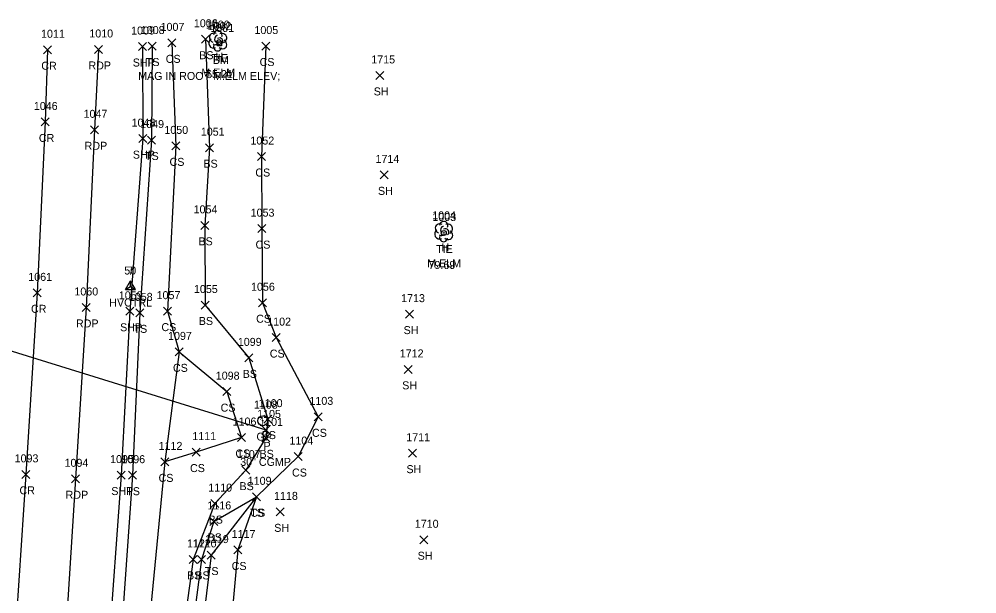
# Model space of a CAD drawing. Extents: x 1443960 to 1446865, y 610387 to 616706.
# Drawn here: x 1446612.8 to 1446852.1, y 611314.4 to 611458.2 of the extents above; entities that cross this region are included whole.
import ezdxf

# ---------------------------------------------------------------- set-up
doc = ezdxf.new("R2010")
doc.units = 0
for name, color, linetype in [('C_A', 7, 'Continuous'), ('C_C', 7, 'Continuous'), ('C_I', 7, 'Continuous'), ('CBP', 7, 'Continuous'), ('CPBM', 7, 'Continuous'), ('CPSM', 7, 'Continuous'), ('D_A', 7, 'Continuous'), ('D_C', 7, 'Continuous'), ('D_I', 7, 'Continuous'), ('D_TIC', 7, 'Continuous'), ('DCP', 7, 'Continuous'), ('L_A', 7, 'Continuous'), ('L_C', 7, 'Continuous'), ('L_I', 7, 'Continuous'), ('L_TIC', 7, 'Continuous'), ('LELB', 7, 'Continuous'), ('LTD', 7, 'Continuous'), ('P_A', 7, 'Continuous'), ('P_I', 7, 'Continuous'), ('P_TIC', 7, 'Continuous'), ('PET', 7, 'Continuous'), ('PRC', 7, 'Continuous'), ('PSP', 7, 'Continuous'), ('R_A', 7, 'Continuous'), ('R_I', 7, 'Continuous'), ('RGP', 7, 'Continuous')]:
    doc.layers.add(name, color=color, linetype=linetype)

msp = doc.modelspace()

# ---------------------------------------------------------------- linework, layer by layer
at = {"layer": 'CBP'}
for centre, radius in [((1446662.7, 611452.41), 0.625), ((1446662.7, 611452.41), 0.0833), ((1446718.89, 611404.66), 0.625), ((1446718.89, 611404.66), 0.0833)]:
    msp.add_circle(centre, radius, dxfattribs=at)
at = {"layer": 'CPBM'}
for p, q in [((1446662.33, 611451.44), (1446662.33, 611452.44)), ((1446662.33, 611452.44), (1446663.33, 611452.44)), ((1446662.83, 611451.94), (1446662.83, 611451.94)), ((1446662.83, 611451.94), (1446662.83, 611451.94)), ((1446663.33, 611452.44), (1446663.33, 611451.44)), ((1446663.33, 611451.44), (1446662.33, 611451.44))]:
    msp.add_line(p, q, dxfattribs=at)
at = {"layer": 'CPSM'}
for p, q in [((1446639.33, 611390.55), (1446640.58, 611392.71)), ((1446639.33, 611390.55), (1446640.58, 611392.71)), ((1446641.83, 611390.55), (1446640.58, 611392.71)), ((1446640.58, 611391.27), (1446640.58, 611392.71)), ((1446641.83, 611390.55), (1446640.58, 611392.71)), ((1446640.58, 611391.27), (1446640.58, 611392.71)), ((1446639.33, 611390.55), (1446640.58, 611391.27)), ((1446639.33, 611390.55), (1446640.58, 611391.27)), ((1446639.33, 611390.55), (1446641.83, 611390.55)), ((1446639.33, 611390.55), (1446641.83, 611390.55)), ((1446640.58, 611391.27), (1446640.58, 611391.27)), ((1446640.58, 611391.27), (1446641.83, 611390.55)), ((1446640.58, 611391.27), (1446640.58, 611391.27)), ((1446640.58, 611391.27), (1446641.83, 611390.55))]:
    msp.add_line(p, q, dxfattribs=at)
at = {"layer": 'D_TIC'}
for points in [[(1446673.45, 611354.4), (1446675.45, 611356.4)], [(1446675.45, 611354.4), (1446673.45, 611356.4)]]:
    msp.add_lwpolyline(points, dxfattribs=at)
at = {"layer": 'DCP'}
msp.add_lwpolyline([(1446557.44, 611391.72), (1446674.45, 611355.4)], dxfattribs=at)
at = {"layer": 'L_TIC'}
for points in [[(1446658.32, 611452.13), (1446660.32, 611454.13)], [(1446660.32, 611452.13), (1446658.32, 611454.13)], [(1446645.01, 611450.43), (1446647.01, 611452.43)], [(1446647.01, 611450.43), (1446645.01, 611452.43)], [(1446649.95, 611451.22), (1446651.95, 611453.22)], [(1446651.95, 611451.22), (1446649.95, 611453.22)], [(1446673.41, 611450.43), (1446675.41, 611452.43)], [(1446675.41, 611450.43), (1446673.41, 611452.43)], [(1446701.89, 611443.07), (1446703.89, 611445.07)], [(1446703.89, 611443.07), (1446701.89, 611445.07)], [(1446644.8, 611426.91), (1446646.8, 611428.91)], [(1446646.8, 611426.91), (1446644.8, 611428.91)], [(1446650.9, 611425.45), (1446652.9, 611427.45)], [(1446652.9, 611425.45), (1446650.9, 611427.45)], [(1446659.37, 611425), (1446661.37, 611427)], [(1446661.37, 611425), (1446659.37, 611427)], [(1446672.33, 611422.78), (1446674.33, 611424.78)], [(1446674.33, 611422.78), (1446672.33, 611424.78)], [(1446702.95, 611418.2), (1446704.95, 611420.2)], [(1446704.95, 611418.2), (1446702.95, 611420.2)], [(1446658.13, 611405.57), (1446660.13, 611407.57)], [(1446660.13, 611405.57), (1446658.13, 611407.57)], [(1446672.4, 611404.75), (1446674.4, 611406.75)], [(1446674.4, 611404.75), (1446672.4, 611406.75)], [(1446658.21, 611385.64), (1446660.21, 611387.64)], [(1446660.21, 611385.64), (1446658.21, 611387.64)], [(1446672.54, 611386.21), (1446674.54, 611388.21)], [(1446674.54, 611386.21), (1446672.54, 611388.21)], [(1446641.94, 611383.68), (1446643.94, 611385.68)], [(1446643.94, 611383.68), (1446641.94, 611385.68)], [(1446648.87, 611384.11), (1446650.87, 611386.11)], [(1446650.87, 611384.11), (1446648.87, 611386.11)], [(1446709.36, 611383.36), (1446711.36, 611385.36)], [(1446711.36, 611383.36), (1446709.36, 611385.36)], [(1446675.96, 611377.49), (1446677.96, 611379.49)], [(1446677.96, 611377.49), (1446675.96, 611379.49)], [(1446651.75, 611373.92), (1446653.75, 611375.92)], [(1446653.75, 611373.92), (1446651.75, 611375.92)], [(1446651.75, 611373.92), (1446653.75, 611375.92)], [(1446653.75, 611373.92), (1446651.75, 611375.92)], [(1446669.19, 611372.42), (1446671.19, 611374.42)], [(1446671.19, 611372.42), (1446669.19, 611374.42)], [(1446709.01, 611369.54), (1446711.01, 611371.54)], [(1446711.01, 611369.54), (1446709.01, 611371.54)], [(1446663.67, 611363.97), (1446665.67, 611365.97)], [(1446665.67, 611363.97), (1446663.67, 611365.97)], [(1446673.94, 611357.1), (1446675.94, 611359.1)], [(1446675.94, 611357.1), (1446673.94, 611359.1)], [(1446686.51, 611357.67), (1446688.51, 611359.67)], [(1446688.51, 611357.67), (1446686.51, 611359.67)], [(1446667.37, 611352.5), (1446669.37, 611354.5)], [(1446669.37, 611352.5), (1446667.37, 611354.5)], [(1446673.39, 611352.41), (1446675.39, 611354.41)], [(1446675.39, 611352.41), (1446673.39, 611354.41)], [(1446656.02, 611348.85), (1446658.02, 611350.85)], [(1446658.02, 611348.85), (1446656.02, 611350.85)], [(1446681.52, 611347.73), (1446683.52, 611349.73)], [(1446683.52, 611347.73), (1446681.52, 611349.73)], [(1446710.08, 611348.58), (1446712.08, 611350.58)], [(1446712.08, 611348.58), (1446710.08, 611350.58)], [(1446648.16, 611346.4), (1446650.16, 611348.4)], [(1446650.16, 611346.4), (1446648.16, 611348.4)], [(1446648.16, 611346.4), (1446650.16, 611348.4)], [(1446650.16, 611346.4), (1446648.16, 611348.4)], [(1446640.12, 611343.07), (1446642.12, 611345.07)], [(1446642.12, 611343.07), (1446640.12, 611345.07)], [(1446668.38, 611344.33), (1446670.38, 611346.33)], [(1446670.38, 611344.33), (1446668.38, 611346.33)], [(1446671.1, 611337.67), (1446673.1, 611339.67)], [(1446673.1, 611337.67), (1446671.1, 611339.67)], [(1446671.1, 611337.67), (1446673.1, 611339.67)], [(1446673.1, 611337.67), (1446671.1, 611339.67)], [(1446660.68, 611335.96), (1446662.68, 611337.96)], [(1446662.68, 611335.96), (1446660.68, 611337.96)], [(1446677.03, 611333.9), (1446679.03, 611335.9)], [(1446679.03, 611333.9), (1446677.03, 611335.9)], [(1446660.42, 611331.51), (1446662.42, 611333.51)], [(1446662.42, 611331.51), (1446660.42, 611333.51)], [(1446712.87, 611326.92), (1446714.87, 611328.92)], [(1446714.87, 611326.92), (1446712.87, 611328.92)], [(1446659.75, 611323.09), (1446661.75, 611325.09)], [(1446661.75, 611323.09), (1446659.75, 611325.09)], [(1446666.43, 611324.36), (1446668.43, 611326.36)], [(1446668.43, 611324.36), (1446666.43, 611326.36)], [(1446655.28, 611322), (1446657.28, 611324)], [(1446657.28, 611322), (1446655.28, 611324)], [(1446657.36, 611322), (1446659.36, 611324)], [(1446659.36, 611322), (1446657.36, 611324)]]:
    msp.add_lwpolyline(points, dxfattribs=at)
at = {"layer": 'LELB'}
for points in [[(1446650.95, 611452.22), (1446651.9, 611426.45), (1446649.87, 611385.11), (1446652.75, 611374.92), (1446649.16, 611347.4), (1446644.4, 611298.29), (1446641.62, 611252.48), (1446636.15, 611208.65), (1446631.11, 611163.63), (1446633.53, 611158.95), (1446637.37, 611162.3), (1446642.9, 611148.76), (1446645.64, 611144.28), (1446654.29, 611138.48), (1446692.29, 611116.85), (1446724.64, 611106.48), (1446767.02, 611093.78), (1446771.54, 611085.7), (1446779.15, 611079.3), (1446804.37, 611061.23), (1446846.91, 611054.82)], [(1446659.32, 611453.13), (1446660.37, 611426), (1446659.13, 611406.57), (1446659.21, 611386.64), (1446670.19, 611373.42), (1446674.94, 611358.1), (1446674.39, 611353.41), (1446669.38, 611345.33), (1446661.68, 611336.96), (1446656.28, 611323), (1446652.61, 611296.67), (1446649.33, 611250.55), (1446643.71, 611210.42), (1446642.98, 611161.02)], [(1446646.01, 611451.43), (1446645.8, 611427.91), (1446642.94, 611384.68), (1446641.12, 611344.07), (1446637.9, 611299.18), (1446633.76, 611254.36), (1446628.53, 611208.76), (1446626.59, 611161.02), (1446631.89, 611151.52), (1446639.4, 611144.52), (1446638.89, 611137.35), (1446641.22, 611135.35), (1446691.88, 611109.53), (1446720.61, 611092.87), (1446765.35, 611070.86), (1446803.04, 611049.45), (1446832.29, 611033.43)], [(1446674.41, 611451.43), (1446673.33, 611423.78), (1446673.4, 611405.75), (1446673.54, 611387.21), (1446676.96, 611378.49), (1446687.51, 611358.67), (1446682.52, 611348.73), (1446672.1, 611338.67), (1446667.43, 611325.36), (1446664.64, 611295.09), (1446664.71, 611246.97), (1446665.06, 611207.83), (1446662.27, 611160.47), (1446692.58, 611128.32), (1446729.03, 611120.7), (1446764.81, 611100.69), (1446774.62, 611095.27), (1446783.7, 611091.47), (1446810.78, 611080.25), (1446852.14, 611066.22)], [(1446652.75, 611374.92), (1446664.67, 611364.97), (1446668.37, 611353.5), (1446657.02, 611349.85), (1446649.16, 611347.4)], [(1446672.1, 611338.67), (1446660.75, 611324.09), (1446657.32, 611296.21), (1446653.24, 611250), (1446649.33, 611209.24), (1446649.16, 611162.92), (1446654.29, 611138.48)], [(1446661.42, 611332.51), (1446672.1, 611338.67)], [(1446661.42, 611332.51), (1446658.36, 611323), (1446654.87, 611296.43), (1446651.95, 611250.23), (1446646.19, 611210.4), (1446642.98, 611161.02)]]:
    msp.add_lwpolyline(points, dxfattribs=at)
at = {"layer": 'LTD'}
for p, q in [((1446662.37, 611452.79), (1446662.37, 611452.79)), ((1446662.37, 611452.79), (1446662.37, 611452.79)), ((1446718.85, 611405.07), (1446718.85, 611405.07)), ((1446718.85, 611405.07), (1446718.85, 611405.07))]:
    msp.add_line(p, q, dxfattribs=at)
for centre in [(1446662.42, 611454.22), (1446718.9, 611406.51)]:
    msp.add_arc(centre, 1.05, 335.5272, 180.9563, dxfattribs=at)
for centre, major_axis, ratio, start_param, end_param in [((1446661.58, 611453.46), (1.21, -0.51), 0.895232, 1.570796, 4.712389), ((1446662.16, 611453.25), (-0.208, -0.792), 0.645439, 3.141593, 6.283185), ((1446663.41, 611453.37), (-1.14, -0.48), 0.949671, 1.570796, 4.712389), ((1446661.29, 611452.08), (0.58, -1.04), 0.959034, 3.141593, 6.283185), ((1446661.91, 611452.04), (-0.625, -0.083), 0.423636, 0, 3.141593), ((1446662.87, 611452.62), (-0.5, 0.667), 0.989748, 3.141593, 6.283185), ((1446663.37, 611451.96), (-1.09, 0.79), 0.841452, 1.570796, 4.712389), ((1446662.37, 611451.29), (0.26, 1.06), 0.942809, 1.570796, 4.712389), ((1446718.06, 611405.74), (1.21, -0.51), 0.895232, 1.570796, 4.712389), ((1446718.64, 611405.53), (-0.208, -0.792), 0.645439, 3.141593, 6.283185), ((1446719.89, 611405.66), (-1.14, -0.48), 0.949671, 1.570796, 4.712389), ((1446717.77, 611404.36), (0.58, -1.04), 0.959034, 3.141593, 6.283185), ((1446718.39, 611404.32), (-0.625, -0.083), 0.423636, 0, 3.141593), ((1446719.35, 611404.91), (-0.5, 0.667), 0.989748, 3.141593, 6.283185), ((1446719.85, 611404.24), (-1.09, 0.79), 0.841452, 1.570796, 4.712389), ((1446718.85, 611403.57), (0.26, 1.06), 0.942809, 1.570796, 4.712389)]:
    msp.add_ellipse(centre, major_axis=major_axis, ratio=ratio, start_param=start_param, end_param=end_param, dxfattribs=at)
at = {"layer": 'P_TIC'}
for points in [[(1446642.6, 611450.3), (1446644.6, 611452.3)], [(1446644.6, 611450.3), (1446642.6, 611452.3)], [(1446618.86, 611449.5), (1446620.86, 611451.5)], [(1446620.86, 611449.5), (1446618.86, 611451.5)], [(1446631.58, 611449.57), (1446633.58, 611451.57)], [(1446633.58, 611449.57), (1446631.58, 611451.57)], [(1446618.25, 611431.43), (1446620.25, 611433.43)], [(1446620.25, 611431.43), (1446618.25, 611433.43)], [(1446630.62, 611429.47), (1446632.62, 611431.47)], [(1446632.62, 611429.47), (1446630.62, 611431.47)], [(1446642.63, 611427.26), (1446644.63, 611429.26)], [(1446644.63, 611427.26), (1446642.63, 611429.26)], [(1446616.28, 611388.69), (1446618.28, 611390.69)], [(1446618.28, 611388.69), (1446616.28, 611390.69)], [(1446628.46, 611385.03), (1446630.46, 611387.03)], [(1446630.46, 611385.03), (1446628.46, 611387.03)], [(1446639.44, 611384.07), (1446641.44, 611386.07)], [(1446641.44, 611384.07), (1446639.44, 611386.07)], [(1446613.4, 611343.28), (1446615.4, 611345.28)], [(1446615.4, 611343.28), (1446613.4, 611345.28)], [(1446625.87, 611342.17), (1446627.87, 611344.17)], [(1446627.87, 611342.17), (1446625.87, 611344.17)], [(1446637.25, 611343.1), (1446639.25, 611345.1)], [(1446639.25, 611343.1), (1446637.25, 611345.1)]]:
    msp.add_lwpolyline(points, dxfattribs=at)
at = {"layer": 'PET'}
msp.add_lwpolyline([(1446632.58, 611450.57), (1446631.62, 611430.47), (1446629.46, 611386.03), (1446626.87, 611343.17), (1446624.08, 611299.75), (1446620.8, 611255.87), (1446617.26, 611209.52), (1446613.17, 611162.1), (1446611.04, 611142.08)], dxfattribs=at)
at = {"layer": 'PRC'}
msp.add_lwpolyline([(1446619.86, 611450.5), (1446619.25, 611432.43), (1446617.28, 611389.69), (1446614.4, 611344.28), (1446611.54, 611300.05), (1446608.09, 611257.25), (1446604.45, 611210.89), (1446600.19, 611163.97), (1446598.97, 611148.35)], dxfattribs=at)
at = {"layer": 'PSP'}
msp.add_lwpolyline([(1446643.6, 611451.3), (1446643.63, 611428.26), (1446640.44, 611385.07), (1446638.25, 611344.1), (1446635.02, 611299.39), (1446631.16, 611255.01), (1446627.07, 611208.74), (1446623.04, 611160.92), (1446621.65, 611145.45), (1446620.1, 611138.33), (1446620.36, 611137.27)], dxfattribs=at)
at = {"layer": 'RGP'}
msp.add_line((1446673.64, 611357.71), (1446673.64, 611357.71), dxfattribs=at)
for radius in [1.25, 0.0833]:
    msp.add_circle((1446673.64, 611357.71), radius, dxfattribs=at)

# ---------------------------------------------------------------- texts
at = {"layer": 'C_A'}
for s, p in [('TIE', (1446660.78, 611447.41)), ('BM', (1446661.15, 611446.94)), ('TIE', (1446716.97, 611399.66)), ('HVCTRL', (1446635.27, 611386.27)), ('HVCTRL', (1446635.27, 611386.27))]:
    msp.add_text(s, height=2, dxfattribs=at).set_placement(p)
at = {"layer": 'C_C'}
for s, p in [('MAG IN ROOT M.ELM ELEV;', (1446642.5, 611442.94)), ('65.21', (1446659.47, 611443.41)), ('79.69', (1446715.09, 611395.66))]:
    msp.add_text(s, height=2, dxfattribs=at).set_placement(p)
at = {"layer": 'C_I'}
for s, p in [('1002', (1446659.85, 611455.41)), ('1001', (1446660.55, 611454.94)), ('1003', (1446716.04, 611407.66)), ('50', (1446639.03, 611394.27)), ('7', (1446640.01, 611394.27))]:
    msp.add_text(s, height=2, dxfattribs=at).set_placement(p)
at = {"layer": 'D_A'}
msp.add_text('P', height=2, dxfattribs=at).set_placement((1446673.82, 611350.4))
at = {"layer": 'D_C'}
msp.add_text('30" CGMP', height=2, dxfattribs=at).set_placement((1446668.01, 611346.4))
at = {"layer": 'D_I'}
msp.add_text('1105', height=2, dxfattribs=at).set_placement((1446672.24, 611358.4))
at = {"layer": 'L_A'}
for s, p in [('BS', (1446657.76, 611448.13)), ('H', (1446661.81, 611447.79)), ('TS', (1446644.42, 611446.43)), ('CS', (1446649.39, 611447.22)), ('CS', (1446672.85, 611446.43)), ('SH', (1446701.38, 611439.07)), ('TS', (1446644.21, 611422.91)), ('CS', (1446650.34, 611421.45)), ('BS', (1446658.81, 611421)), ('CS', (1446671.78, 611418.78)), ('SH', (1446702.44, 611414.2)), ('BS', (1446657.57, 611401.57)), ('CS', (1446671.84, 611400.75)), ('H', (1446718.29, 611400.07)), ('BS', (1446657.65, 611381.64)), ('CS', (1446671.98, 611382.21)), ('TS', (1446641.35, 611379.68)), ('CS', (1446648.31, 611380.11)), ('SH', (1446708.85, 611379.36)), ('CS', (1446675.4, 611373.49)), ('CS', (1446651.19, 611369.92)), ('CS', (1446651.19, 611369.92)), ('BS', (1446668.63, 611368.42)), ('SH', (1446708.5, 611365.54)), ('CS', (1446663.11, 611359.97)), ('BS', (1446673.38, 611353.1)), ('CS', (1446685.95, 611353.67)), ('CS', (1446666.81, 611348.5)), ('BS', (1446672.83, 611348.41)), ('CS', (1446655.46, 611344.85)), ('SH', (1446709.57, 611344.58)), ('CS', (1446647.6, 611342.4)), ('CS', (1446647.6, 611342.4)), ('CS', (1446680.96, 611343.73)), ('BS', (1446667.82, 611340.33)), ('TS', (1446639.53, 611339.07)), ('TS', (1446670.51, 611333.67)), ('CS', (1446670.54, 611333.67)), ('BS', (1446660.12, 611331.96)), ('SH', (1446676.51, 611329.9)), ('BS', (1446659.86, 611327.51)), ('SH', (1446712.36, 611322.92)), ('TS', (1446659.16, 611319.09)), ('CS', (1446665.87, 611320.36)), ('BS', (1446654.72, 611318)), ('BS', (1446656.8, 611318))]:
    msp.add_text(s, height=2, dxfattribs=at).set_placement(p)
at = {"layer": 'L_C'}
for p in [(1446658.28, 611443.79), (1446714.76, 611396.07)]:
    msp.add_text('M.ELM', height=2, dxfattribs=at).set_placement(p)
at = {"layer": 'L_I'}
for s, p in [('1007', (1446648.1, 611455.22)), ('1006', (1446656.42, 611456.13)), ('1000', (1446659.44, 611455.79)), ('1008', (1446643.16, 611454.43)), ('1005', (1446671.56, 611454.43)), ('1715', (1446700.77, 611447.07)), ('1049', (1446643.02, 611430.91)), ('1050', (1446649.05, 611429.45)), ('1051', (1446658.16, 611429)), ('1052', (1446670.56, 611426.78)), ('1714', (1446701.83, 611422.2)), ('1054', (1446656.36, 611409.57)), ('1053', (1446670.62, 611408.75)), ('1004', (1446716, 611408.07)), ('1056', (1446670.71, 611390.21)), ('1058', (1446640.17, 611387.68)), ('1057', (1446647.1, 611388.11)), ('1055', (1446656.44, 611389.64)), ('1713', (1446708.23, 611387.36)), ('1102', (1446674.76, 611381.49)), ('1097', (1446649.97, 611377.92)), ('1097', (1446649.97, 611377.92)), ('1099', (1446667.41, 611376.42)), ('1712', (1446707.89, 611373.54)), ('1098', (1446661.9, 611367.97)), ('1103', (1446685.31, 611361.67)), ('1100', (1446672.65, 611361.1)), ('1106', (1446666.11, 611356.5)), ('1101', (1446672.75, 611356.41)), ('1111', (1446656.03, 611352.85)), ('1104', (1446680.31, 611351.73)), ('1711', (1446709.52, 611352.58)), ('1112', (1446647.6, 611350.4)), ('1112', (1446647.6, 611350.4)), ('1096', (1446638.29, 611347.07)), ('1107', (1446667.18, 611348.33)), ('1110', (1446660.03, 611339.96)), ('1109', (1446669.89, 611341.67)), ('1109', (1446669.89, 611341.67)), ('1118', (1446676.47, 611337.9)), ('1116', (1446659.8, 611335.51)), ('1710', (1446711.65, 611330.92)), ('1117', (1446665.87, 611328.36)), ('1121', (1446654.72, 611326)), ('1120', (1446656.15, 611326)), ('1119', (1446659.19, 611327.09))]:
    msp.add_text(s, height=2, dxfattribs=at).set_placement(p)
at = {"layer": 'P_A'}
for s, p in [('CR', (1446618.29, 611445.5)), ('RDP', (1446630.07, 611445.57)), ('SHP', (1446641.14, 611446.3)), ('CR', (1446617.68, 611427.43)), ('RDP', (1446629.11, 611425.47)), ('SHP', (1446641.17, 611423.26)), ('CR', (1446615.71, 611384.69)), ('RDP', (1446626.95, 611381.03)), ('SHP', (1446637.98, 611380.07)), ('CR', (1446612.83, 611339.28)), ('RDP', (1446624.36, 611338.17)), ('SHP', (1446635.78, 611339.1))]:
    msp.add_text(s, height=2, dxfattribs=at).set_placement(p)
at = {"layer": 'P_I'}
for s, p in [('1011', (1446618.22, 611453.5)), ('1010', (1446630.29, 611453.57)), ('1009', (1446640.74, 611454.3)), ('1046', (1446616.42, 611435.43)), ('1047', (1446628.85, 611433.47)), ('1048', (1446640.86, 611431.26)), ('1061', (1446615.03, 611392.69)), ('1060', (1446626.56, 611389.03)), ('1059', (1446637.66, 611388.07)), ('1093', (1446611.62, 611347.28)), ('1095', (1446635.48, 611347.1)), ('1094', (1446624.1, 611346.17))]:
    msp.add_text(s, height=2, dxfattribs=at).set_placement(p)
at = {"layer": 'R_A'}
msp.add_text('GP', height=2, dxfattribs=at).set_placement((1446672.07, 611352.71))
at = {"layer": 'R_I'}
msp.add_text('1108', height=2, dxfattribs=at).set_placement((1446671.43, 611360.71))

doc.saveas('drawing.dxf')
